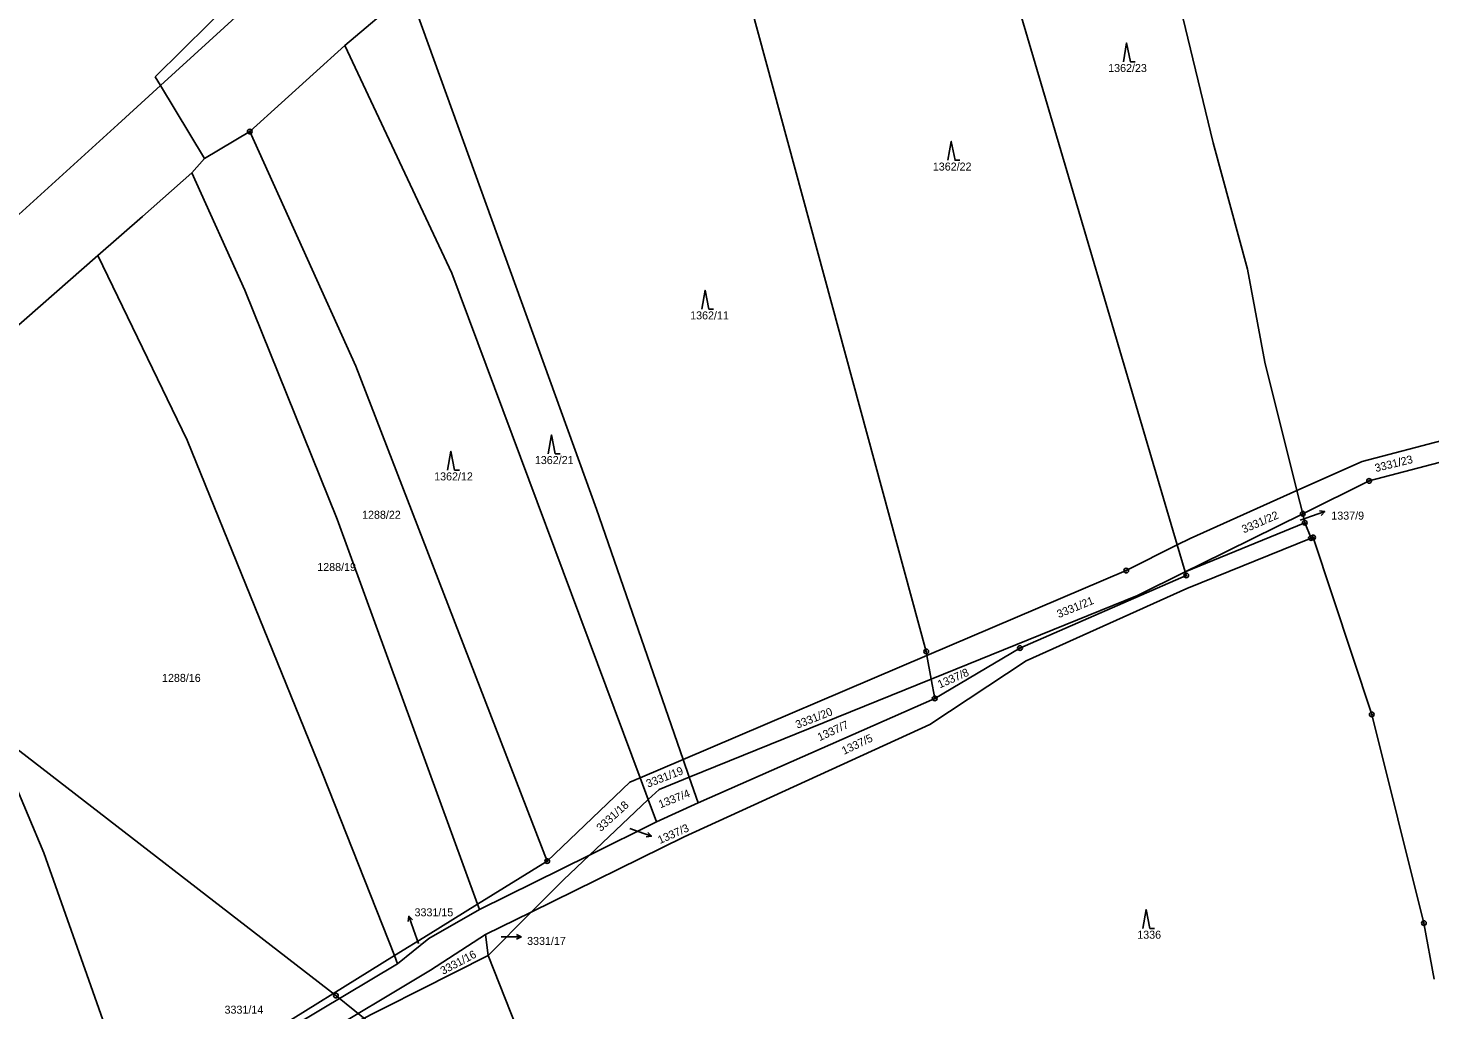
# Model space of a CAD drawing. Extents: x -763205 to -760228, y -1155311 to -1152844.
# Drawn here: x -761051 to -760753.2, y -1154768.5 to -1154559.9 of the extents above; entities that cross this region are included whole.
import ezdxf

# ---------------------------------------------------------------- set-up
doc = ezdxf.new("R2010")
doc.units = 0
for name, color, linetype in [('Vrstva 1', 7, 'Continuous'), ('Vrstva 12', 7, 'Continuous'), ('Vrstva 16', 7, 'Continuous'), ('Vrstva 18', 7, 'Continuous'), ('Vrstva 24', 7, 'Continuous'), ('Vrstva 25', 7, 'Continuous'), ('Vrstva 26', 7, 'Continuous'), ('Vrstva 6', 7, 'Continuous')]:
    doc.layers.add(name, color=color, linetype=linetype)

msp = doc.modelspace()

# ---------------------------------------------------------------- linework, layer by layer
at = {"layer": 'Vrstva 1'}
for p, q in [((-761024.03, -1154570.3), (-760949.92, -1154497.13)), ((-760844.39, -1154542.64), (-760806.91, -1154669.75)), ((-760897.41, -1154555.51), (-760860.25, -1154692.37)), ((-761024.03, -1154570.3), (-761022.9, -1154572.17)), ((-761022.9, -1154572.17), (-761013.58, -1154587.69)), ((-761013.58, -1154587.69), (-761003.93, -1154581.93)), ((-761003.93, -1154581.93), (-760981.41, -1154631.75)), ((-760981.41, -1154631.75), (-760940.75, -1154736.88)), ((-760767.66, -1154652.01), (-760749.33, -1154647.21)), ((-760781.49, -1154658.21), (-760767.66, -1154652.01)), ((-760766.18, -1154656.14), (-760748.29, -1154651.48)), ((-760780.27, -1154663.1), (-760766.18, -1154656.14)), ((-760804.21, -1154668.4), (-760781.49, -1154658.21)), ((-760801.74, -1154673.72), (-760780.27, -1154663.1)), ((-760780.27, -1154663.1), (-760779.84, -1154665.02)), ((-760779.84, -1154665.02), (-760778.51, -1154668.27)), ((-760806.91, -1154669.75), (-760804.21, -1154668.4)), ((-760778.51, -1154668.27), (-760778.07, -1154668.15)), ((-760778.07, -1154668.15), (-760765.61, -1154705.73)), ((-760817.76, -1154675.18), (-760806.91, -1154669.75)), ((-760806.91, -1154669.75), (-760805.23, -1154675.44)), ((-760805.23, -1154675.44), (-760801.74, -1154673.72)), ((-760860.1, -1154693.22), (-760817.76, -1154675.18)), ((-760840.33, -1154691.65), (-760805, -1154676.21)), ((-760815.37, -1154680.45), (-760805.23, -1154675.44)), ((-760859.19, -1154698.22), (-760815.37, -1154680.45)), ((-760858.45, -1154702.34), (-760840.33, -1154691.65)), ((-760911.89, -1154715.29), (-760860.1, -1154693.22)), ((-760860.1, -1154693.22), (-760859.19, -1154698.22)), ((-760910.59, -1154719.07), (-760859.19, -1154698.22)), ((-760859.19, -1154698.22), (-760858.45, -1154702.34)), ((-760765.61, -1154705.73), (-760754.52, -1154750.05)), ((-760921.02, -1154719.18), (-760911.89, -1154715.29)), ((-760923.2, -1154720.11), (-760921.02, -1154719.18)), ((-760916.98, -1154721.66), (-760910.59, -1154719.07)), ((-760940.75, -1154736.88), (-760923.2, -1154720.11)), ((-760919.28, -1154723.84), (-760916.98, -1154721.66)), ((-760931.79, -1154735.64), (-760919.28, -1154723.84)), ((-760955.54, -1154746.05), (-760940.75, -1154736.88)), ((-760937.32, -1154740.86), (-760931.79, -1154735.64)), ((-760944.15, -1154747.73), (-760937.32, -1154740.86)), ((-760966.04, -1154752.55), (-760955.54, -1154746.05)), ((-760953.29, -1154756.91), (-760944.15, -1154747.73)), ((-760754.52, -1154750.05), (-760752.34, -1154761.96)), ((-760973.16, -1154756.96), (-760966.04, -1154752.55)), ((-761004.98, -1154776.68), (-760973.16, -1154756.96)), ((-760998.25, -1154779.61), (-760953.29, -1154756.91)), ((-760953.29, -1154756.91), (-760932.94, -1154808.61))]:
    msp.add_line(p, q, dxfattribs=at)
at = {"layer": 'Vrstva 12'}
for p, q in [((-760985.64, -1154765.47), (-761056.55, -1154710.65)), ((-760934.17, -1154806.8), (-760985.64, -1154765.47))]:
    msp.add_line(p, q, dxfattribs=at)
at = {"layer": 'Vrstva 16'}
for p, q in [((-760775.593, -1154662.663), (-760778.43, -1154663.64)), ((-760780.85, -1154664.47), (-760778.43, -1154663.64)), ((-760923.23, -1154729.97), (-760921.43, -1154730.61)), ((-760918.604, -1154731.617), (-760921.43, -1154730.61)), ((-760970.175, -1154748.62), (-760969.18, -1154751.45)), ((-760968.13, -1154754.42), (-760969.18, -1154751.45)), ((-760950.5, -1154753), (-760949.26, -1154753)), ((-760946.26, -1154753.001), (-760949.26, -1154753))]:
    msp.add_line(p, q, dxfattribs=at)
for points in [[(-760776.702, -1154662.516), (-760775.593, -1154662.663), (-760776.376, -1154663.462)], [(-760919.378, -1154730.81), (-760918.604, -1154731.617), (-760919.714, -1154731.752)], [(-760970.315, -1154749.729), (-760970.175, -1154748.62), (-760969.371, -1154749.397)], [(-760947.26, -1154752.501), (-760946.26, -1154753.001), (-760947.26, -1154753.501)]]:
    msp.add_lwpolyline(points, dxfattribs=at)
at = {"layer": 'Vrstva 24'}
for centre, radius in [((-761003.93, -1154581.93), 0.5), ((-761003.93, -1154581.93), 0.1), ((-760766.18, -1154656.14), 0.5), ((-760766.18, -1154656.14), 0.1), ((-760780.27, -1154663.1), 0.5), ((-760780.27, -1154663.1), 0.1), ((-760779.84, -1154665.02), 0.5), ((-760779.84, -1154665.02), 0.1), ((-760778.51, -1154668.27), 0.5), ((-760778.51, -1154668.27), 0.1), ((-760778.07, -1154668.15), 0.5), ((-760778.07, -1154668.15), 0.1), ((-760817.76, -1154675.18), 0.5), ((-760817.76, -1154675.18), 0.1), ((-760805, -1154676.21), 0.5), ((-760805, -1154676.21), 0.1), ((-760860.25, -1154692.37), 0.5), ((-760860.25, -1154692.37), 0.1), ((-760840.33, -1154691.65), 0.5), ((-760840.33, -1154691.65), 0.1), ((-760858.45, -1154702.34), 0.5), ((-760858.45, -1154702.34), 0.1), ((-760765.61, -1154705.73), 0.5), ((-760765.61, -1154705.73), 0.1), ((-760940.75, -1154736.88), 0.5), ((-760940.75, -1154736.88), 0.1), ((-760754.52, -1154750.05), 0.5), ((-760754.52, -1154750.05), 0.1)]:
    msp.add_circle(centre, radius, dxfattribs=at)
at = {"layer": 'Vrstva 25'}
for points in [[(-760818.37, -1154567.09), (-760817.67, -1154563.09), (-760816.87, -1154567.09), (-760815.87, -1154567.09)], [(-760855.63, -1154588.02), (-760854.93, -1154584.02), (-760854.13, -1154588.02), (-760853.13, -1154588.02)], [(-760907.92, -1154619.63), (-760907.22, -1154615.63), (-760906.42, -1154619.63), (-760905.42, -1154619.63)], [(-760940.53, -1154650.36), (-760939.83, -1154646.36), (-760939.03, -1154650.36), (-760938.03, -1154650.36)], [(-760961.92, -1154653.83), (-760961.22, -1154649.83), (-760960.42, -1154653.83), (-760959.42, -1154653.83)], [(-760814.23, -1154751.18), (-760813.53, -1154747.18), (-760812.73, -1154751.18), (-760811.73, -1154751.18)]]:
    msp.add_lwpolyline(points, dxfattribs=at)
at = {"layer": 'Vrstva 26'}
msp.add_circle((-760985.64, -1154765.47), 0.5, dxfattribs=at)
at = {"layer": 'Vrstva 6'}
for p, q in [((-760831.95, -1154449.38), (-760799.32, -1154584.31)), ((-761022.9, -1154572.17), (-760935.94, -1154492.79)), ((-760983.74, -1154563.65), (-760970.06, -1154552.07)), ((-760970.06, -1154552.07), (-760930.28, -1154662.11)), ((-761003.93, -1154581.93), (-760983.74, -1154563.65)), ((-760983.74, -1154563.65), (-760961, -1154611.99)), ((-761031.95, -1154580.43), (-761022.9, -1154572.17)), ((-761076.68, -1154621), (-761031.95, -1154580.43)), ((-760799.32, -1154584.31), (-760791.99, -1154611.19)), ((-761016.25, -1154590.71), (-761013.58, -1154587.69)), ((-761026.75, -1154600), (-761016.25, -1154590.71)), ((-761016.25, -1154590.71), (-761004.97, -1154615.59)), ((-761036.2, -1154608.23), (-761026.75, -1154600)), ((-761074.85, -1154642.19), (-761036.2, -1154608.23)), ((-761036.2, -1154608.23), (-761017.22, -1154647.47)), ((-760961, -1154611.99), (-760921.02, -1154719.18)), ((-760791.99, -1154611.19), (-760788.29, -1154630.92)), ((-761004.97, -1154615.59), (-760985.34, -1154664.27)), ((-760788.29, -1154630.92), (-760781.49, -1154658.21)), ((-761017.22, -1154647.47), (-760988.51, -1154718.26)), ((-760781.49, -1154658.21), (-760780.27, -1154663.1)), ((-760930.28, -1154662.11), (-760911.89, -1154715.29)), ((-760985.34, -1154664.27), (-760955.54, -1154746.05)), ((-760805.23, -1154675.44), (-760779.84, -1154665.02)), ((-760804.89, -1154679), (-760778.51, -1154668.27)), ((-760805.23, -1154675.44), (-760805, -1154676.21)), ((-760839, -1154694.38), (-760804.89, -1154679)), ((-760860.25, -1154692.37), (-760860.1, -1154693.22)), ((-761064.43, -1154695.35), (-761047.7, -1154735.12)), ((-760859.46, -1154707.89), (-760839, -1154694.38)), ((-760908.71, -1154724.5), (-760858.45, -1154702.34)), ((-760911.64, -1154731.74), (-760859.46, -1154707.89)), ((-760911.89, -1154715.29), (-760910.59, -1154719.07)), ((-760988.51, -1154718.26), (-760973.16, -1154756.96)), ((-760921.02, -1154719.18), (-760919.28, -1154723.84)), ((-760910.59, -1154719.07), (-760908.71, -1154724.5)), ((-760919.28, -1154723.84), (-760917.51, -1154728.58)), ((-760917.51, -1154728.58), (-760908.71, -1154724.5)), ((-760931.79, -1154735.64), (-760917.51, -1154728.58)), ((-760944.15, -1154747.73), (-760911.64, -1154731.74)), ((-761047.7, -1154735.12), (-761028.69, -1154788.71)), ((-760955.13, -1154747.18), (-760931.79, -1154735.64)), ((-760955.54, -1154746.05), (-760955.13, -1154747.18)), ((-760965.91, -1154753.36), (-760955.13, -1154747.18)), ((-760953.86, -1154752.5), (-760944.15, -1154747.73)), ((-760972.57, -1154758.7), (-760965.91, -1154753.36)), ((-760965.58, -1154760.07), (-760953.86, -1154752.5)), ((-760953.86, -1154752.5), (-760953.29, -1154756.91)), ((-760973.16, -1154756.96), (-760972.57, -1154758.7)), ((-761012.22, -1154782.37), (-760972.57, -1154758.7)), ((-760998.25, -1154779.61), (-760965.58, -1154760.07))]:
    msp.add_line(p, q, dxfattribs=at)

# ---------------------------------------------------------------- texts
at = {"layer": 'Vrstva 16'}
for s, p in [('1337/9', (-760774.197, -1154664.36)), ('3331/15', (-760968.933, -1154748.62)), ('3331/17', (-760945.023, -1154754.7)), ('3331/14', (-761009.292, -1154769.3))]:
    msp.add_text(s, height=1.7, dxfattribs=at).set_placement(p)
msp.add_text('1337/3', height=1.7, rotation=23.89234, dxfattribs=at).set_placement((-760916.822, -1154733.285))
at = {"layer": 'Vrstva 18'}
for s, height, p in [('1362/23', 1.7, (-760821.597, -1154569.29)), ('1362/22', 1.7, (-760858.847, -1154590.22)), ('1362/11', 1.7, (-760910.387, -1154621.83)), ('1362/21', 1.7, (-760943.377, -1154652.56)), ('1362/12', 1.7, (-760964.767, -1154656.03)), ('1288/22', 1.7, (-760980.077, -1154664.18)), ('1337/9', 0.1, (-760780.827, -1154664.47)), ('1288/19', 1.7, (-760989.597, -1154675.28)), ('1288/16', 1.7, (-761022.577, -1154698.83)), ('1337/3', 0.1, (-760923.207, -1154729.97)), ('1336', 1.7, (-760815.417, -1154753.38)), ('3331/15', 0.1, (-760968.116, -1154754.42)), ('3331/17', 0.1, (-760950.486, -1154753))]:
    msp.add_text(s, height=height, dxfattribs=at).set_placement(p)
for s, rotation, p in [('3331/23', 13.98017, (-760764.73, -1154654.273)), ('3331/22', 23.54857, (-760792.772, -1154667.295)), ('3331/21', 22.34535, (-760832.08, -1154685.3)), ('1337/8', 23.83504, (-760857.361, -1154700.221)), ('3331/20', 21.37133, (-760887.629, -1154708.793)), ('1337/7', 24.80907, (-760882.874, -1154711.435)), ('1337/5', 25.55392, (-760877.696, -1154714.341)), ('3331/19', 21.19944, (-760919.349, -1154721.314)), ('1337/4', 21.42862, (-760916.724, -1154725.697)), ('3331/18', 42.16969, (-760929.364, -1154730.721)), ('3331/16', 27.90304, (-760962.9, -1154761.079))]:
    msp.add_text(s, height=1.7, rotation=rotation, dxfattribs=at).set_placement(p)

doc.saveas('drawing.dxf')
